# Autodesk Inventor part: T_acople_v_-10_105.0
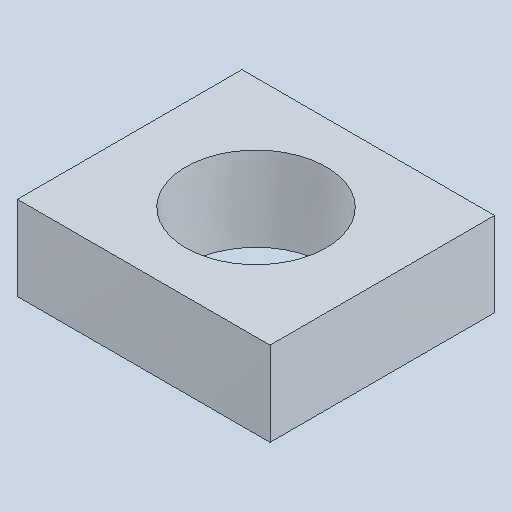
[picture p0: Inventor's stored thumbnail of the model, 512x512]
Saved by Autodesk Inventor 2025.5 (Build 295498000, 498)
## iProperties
Created: 2026-10
Part Number: T_acople_v_-10_105.0
Material: Genérico
Document SubType Name: Modeling
Designer: Luis M
Density: 1 g/cm^3
Appearance: Valor por defecto
Author: Luis M
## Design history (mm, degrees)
feature "Base1"
node "Sólido1"
